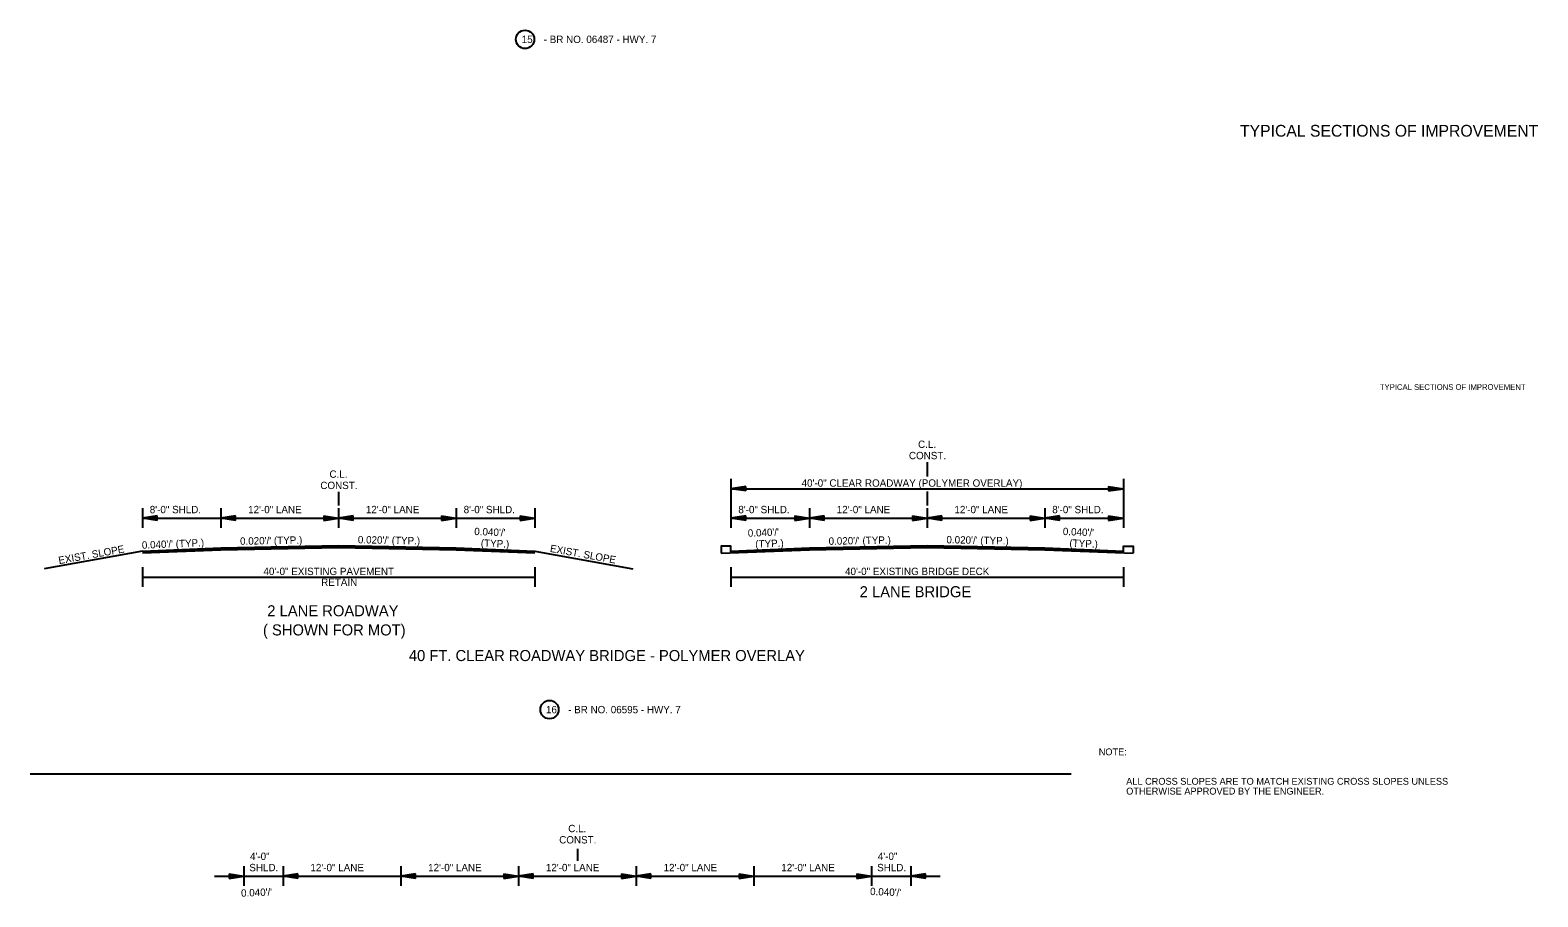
# Model space of a CAD drawing. Extents: x 550980 to 1930787, y -1972975 to 596640.
# Drawn here: x 551009 to 552546, y -1952456 to -1951574 of the extents above; entities that cross this region are included whole.
import ezdxf

# ---------------------------------------------------------------- set-up
doc = ezdxf.new("R2010")
doc.units = 0
for name, color, linetype in [('R_Border', 7, 'Continuous'), ('R_Border Notes', 7, 'Continuous'), ('R_Draft', 7, 'Continuous'), ('S_AREA_CALC', 7, 'Continuous')]:
    doc.layers.add(name, color=color, linetype=linetype)

# ---------------------------------------------------------------- blocks, each defined once
blk = doc.blocks.new('BPPOLY')
at = {"layer": 'R_Border'}
blk.add_circle((0, 0), 9.34, dxfattribs=at)
blk = doc.blocks.new('ARROW')
at = {"layer": 'R_Draft'}
for p, q in [((-2, 0.3), (0, 0)), ((-2, 0.3), (-2, -0.3)), ((-2, 0.25), (-0.334, 0)), ((-2, 0.199), (-0.678, 0)), ((-2, 0.149), (-1.011, 0)), ((-2, 0.097), (-1.35, 0)), ((-2, 0.047), (-1.684, 0)), ((-2, -0.3), (0, 0)), ((-2, -0.098), (-1.35, 0)), ((-2, -0.199), (-0.678, 0)), ((-2, -0.25), (-0.334, 0)), ((-2, -0.149), (-1.011, 0)), ((-2, -0.047), (-1.684, 0))]:
    blk.add_line(p, q, dxfattribs=at)

msp = doc.modelspace()

# ---------------------------------------------------------------- linework, layer by layer
at = {"layer": 'R_Border'}
for p, q in [((551923.4, -1952013.7), (551923.4, -1952028.2)), ((551723.4, -1952030.7), (551723.4, -1952080.7)), ((551723.4, -1952040.7), (552123.4, -1952040.7)), ((552123.4, -1952030.7), (552123.4, -1952080.7)), ((551323.4, -1952043.9), (551323.4, -1952057.7)), ((551923.4, -1952043.7), (551923.4, -1952057.7)), ((551123.4, -1952060.7), (551123.4, -1952080.7)), ((551123.4, -1952070.7), (551523.4, -1952070.7)), ((551203.4, -1952060.7), (551203.4, -1952080.7)), ((551323.4, -1952060.7), (551323.4, -1952080.7)), ((551443.4, -1952060.7), (551443.4, -1952080.7)), ((551523.4, -1952060.7), (551523.4, -1952080.7)), ((551723.4, -1952070.7), (552123.4, -1952070.7)), ((551803.4, -1952060.7), (551803.4, -1952080.7)), ((551923.4, -1952060.7), (551923.4, -1952080.7)), ((552043.4, -1952060.7), (552043.4, -1952080.7)), ((551123.4, -1952104.3), (551023.4, -1952122.3)), ((551523.4, -1952104.3), (551623.4, -1952122.3)), ((551123.4, -1952120.7), (551123.4, -1952140.7)), ((551123.4, -1952130.7), (551523.4, -1952130.7)), ((551523.4, -1952120.7), (551523.4, -1952140.7)), ((551723.4, -1952120.7), (551723.4, -1952140.7)), ((551723.4, -1952130.7), (552123.4, -1952130.7)), ((552123.4, -1952120.7), (552123.4, -1952140.7)), ((551009, -1952331.3), (552070.2, -1952331.3)), ((551566.8, -1952407.6), (551566.8, -1952419.7)), ((551226.8, -1952425.4), (551226.8, -1952445.4)), ((551266.8, -1952425.4), (551266.8, -1952445.4)), ((551386.8, -1952425.4), (551386.8, -1952445.4)), ((551506.8, -1952425.4), (551506.8, -1952445.4)), ((551626.8, -1952425.4), (551626.8, -1952445.4)), ((551746.8, -1952425.4), (551746.8, -1952445.4)), ((551866.8, -1952425.4), (551866.8, -1952445.4)), ((551906.8, -1952425.4), (551906.8, -1952445.4)), ((551196.8, -1952435.4), (551936.8, -1952435.4))]:
    msp.add_line(p, q, dxfattribs=at)
for points in [[(551123.4, -1952104.3), (551203.4, -1952101.1), (551323.4, -1952098.7), (551443.4, -1952101.1), (551523.4, -1952104.3)], [(551123.4, -1952104.6), (551203.4, -1952101.4), (551323.4, -1952099), (551443.4, -1952101.4), (551523.4, -1952104.6)], [(551123.4, -1952104.9), (551203.4, -1952101.7), (551323.4, -1952099.3), (551443.4, -1952101.7), (551523.4, -1952104.9)], [(551123.4, -1952105.2), (551203.4, -1952102), (551323.4, -1952099.6), (551443.4, -1952102), (551523.4, -1952105.2)], [(551123.4, -1952105.5), (551203.4, -1952102.3), (551323.4, -1952099.9), (551443.4, -1952102.3), (551523.4, -1952105.5)], [(551123.4, -1952105.8), (551203.4, -1952102.6), (551323.4, -1952100.2), (551443.4, -1952102.6), (551523.4, -1952105.8)], [(551123.4, -1952106.1), (551203.4, -1952102.9), (551323.4, -1952100.5), (551443.4, -1952102.9), (551523.4, -1952106.1)], [(551723.4, -1952105.8), (551723.4, -1952099.3), (551713.4, -1952099.3), (551713.4, -1952106.5)], [(551713.4, -1952106.5), (551803.4, -1952102.9), (551923.4, -1952100.5), (552043.4, -1952102.9), (552133.4, -1952106.5)], [(551723.4, -1952104.3), (551803.4, -1952101.1), (551923.4, -1952098.7), (552043.4, -1952101.1), (552123.4, -1952104.3)], [(551723.4, -1952104.6), (551803.4, -1952101.4), (551923.4, -1952099), (552043.4, -1952101.4), (552123.4, -1952104.6)], [(551723.4, -1952104.9), (551803.4, -1952101.7), (551923.4, -1952099.3), (552043.4, -1952101.7), (552123.4, -1952104.9)], [(551723.4, -1952105.2), (551803.4, -1952102), (551923.4, -1952099.6), (552043.4, -1952102), (552123.4, -1952105.2)], [(551723.4, -1952105.5), (551803.4, -1952102.3), (551923.4, -1952099.9), (552043.4, -1952102.3), (552123.4, -1952105.5)], [(551723.4, -1952105.8), (551803.4, -1952102.6), (551923.4, -1952100.2), (552043.4, -1952102.6), (552123.4, -1952105.8)], [(552123.4, -1952106.5), (552123.4, -1952099.3), (552133.4, -1952099.3), (552133.4, -1952106.5)]]:
    msp.add_lwpolyline(points, dxfattribs=at)

# ---------------------------------------------------------------- block references
for p in [(551513.5, -1951583), (551538.4, -1952265.7)]:
    msp.add_blockref('BPPOLY', p, dxfattribs=at)
at = {"layer": 'R_Border', "xscale": 7.5, "yscale": 7.5, "rotation": 180}
for p in [(551723.4, -1952040.7), (551123.4, -1952070.7), (551203.4, -1952070.7), (551323.4, -1952070.7), (551723.4, -1952070.7), (551803.4, -1952070.7), (551923.4, -1952070.7), (552043.4, -1952070.7), (551266.8, -1952435.4), (551386.8, -1952435.4), (551506.8, -1952435.4), (551626.8, -1952435.4), (551906.8, -1952435.4)]:
    msp.add_blockref('ARROW', p, dxfattribs=at)
at = {"layer": 'R_Border', "xscale": 7.5, "yscale": 7.5}
for p in [(552123.4, -1952040.7), (551323.4, -1952070.7), (551443.4, -1952070.7), (551523.4, -1952070.7), (551803.4, -1952070.7), (551923.4, -1952070.7), (552043.4, -1952070.7), (552123.4, -1952070.7), (551226.8, -1952435.4), (551506.8, -1952435.4), (551626.8, -1952435.4), (551746.8, -1952435.4), (551866.8, -1952435.4)]:
    msp.add_blockref('ARROW', p, dxfattribs=at)

# ---------------------------------------------------------------- texts
at = {"layer": 'R_Border'}
for s, height, p in [('15', 7.5, (551510.1, -1951586.7)), ('- BR NO. 06487 - HWY. 7', 7.5, (551532.5, -1951586.7)), ('C.L.', 7.5, (551914.1, -1951999.2)), ('CONST.', 7.5, (551904.8, -1952010.7)), ('C.L.', 7.5, (551314.1, -1952029.6)), ('CONST.', 7.5, (551304.8, -1952041.1)), ('40\'-0" CLEAR ROADWAY (POLYMER OVERLAY)', 7.5, (551795.4, -1952038.7)), ('8\'-0" SHLD.', 7.5, (551130.9, -1952065.7)), ('12\'-0" LANE', 7.5, (551231.2, -1952065.7)), ('12\'-0" LANE', 7.5, (551351.2, -1952065.7)), ('8\'-0" SHLD.', 7.5, (551450.9, -1952065.7)), ('8\'-0" SHLD.', 7.5, (551730.9, -1952065.7)), ('12\'-0" LANE', 7.5, (551831.2, -1952065.7)), ('12\'-0" LANE', 7.5, (551951.2, -1952065.7)), ('8\'-0" SHLD.', 7.5, (552050.9, -1952065.7)), ('40\'-0" EXISTING PAVEMENT', 7.5, (551246.8, -1952128.7)), ('RETAIN', 7.5, (551305.6, -1952139.7)), ('40\'-0" EXISTING BRIDGE DECK', 7.5, (551839.7, -1952128.7)), ('2 LANE BRIDGE ', 11.25, (551854.6, -1952151.3)), ('2 LANE ROADWAY', 11.25, (551250.7, -1952170.7)), ('( SHOWN FOR MOT)', 11.25, (551246.3, -1952190.2)), ('40 FT. CLEAR ROADWAY BRIDGE - POLYMER OVERLAY', 11.25, (551395, -1952216.3)), ('16', 7.5, (551534.8, -1952269.5)), ('- BR NO. 06595 - HWY. 7', 7.5, (551557.4, -1952269.5)), ('CONST.', 7.5, (551548.3, -1952402.1)), ('C.L.', 7.5, (551557.5, -1952390.6)), ('4\'-0"', 7.5, (551233.1, -1952418.9)), ('4\'-0"', 7.5, (551873.1, -1952418.9)), ('SHLD.', 7.5, (551232.4, -1952430.4)), ('12\'-0" LANE', 7.5, (551294.7, -1952430.4)), ('12\'-0" LANE', 7.5, (551414.7, -1952430.4)), ('12\'-0" LANE', 7.5, (551534.7, -1952430.4)), ('12\'-0" LANE', 7.5, (551654.7, -1952430.4)), ('12\'-0" LANE', 7.5, (551774.7, -1952430.4)), ('SHLD.', 7.5, (551872.4, -1952430.4))]:
    msp.add_text(s, height=height, dxfattribs=at).set_placement(p)
for s, height, rotation, p in [('TYPICAL SECTIONS OF IMPROVEMENT', 12, 360, (552242.3, -1951682.1)), ("0.020'/' (TYP.)", 7.5, 1.1458, (551223, -1952097.9)), ("0.020'/' (TYP.)", 7.5, 358.8542, (551343, -1952096.3)), ("0.040'/'", 7.5, 357.7084, (551461.6, -1952087.9)), ("0.040'/'", 7.5, 2.2916, (551740.7, -1952089.7)), ("0.020'/' (TYP.)", 7.5, 1.1458, (551823, -1952097.9)), ("0.020'/' (TYP.)", 7.5, 358.8542, (551943, -1952096.3)), ("0.040'/'", 7.5, 357.7084, (552061.6, -1952087.9)), ('EXIST. SLOPE', 7.5, 10.204, (551038.5, -1952117.6)), ("0.040'/' (TYP.)", 7.5, 2.2916, (551123, -1952101.9)), ('(TYP.)', 7.5, 357.7084, (551468.3, -1952099.7)), ('EXIST. SLOPE', 7.5, 349.796, (551538.5, -1952105)), ('(TYP.)', 7.5, 2.2916, (551748.3, -1952100.9)), ('(TYP.)', 7.5, 357.7084, (552068.3, -1952099.7)), ("0.040'/'", 7.5, 2.2916, (551224.1, -1952456.4)), ("0.040'/'", 7.5, 357.7084, (551865.1, -1952454.6))]:
    msp.add_text(s, height=height, rotation=rotation, dxfattribs=at).set_placement(p)
at = {"layer": 'R_Border Notes'}
for s, p in [('NOTE: ', (552098.3, -1952312.3)), ('ALL CROSS SLOPES ARE TO MATCH EXISTING CROSS SLOPES UNLESS ', (552126.3, -1952342.3)), ('OTHERWISE APPROVED BY THE ENGINEER.', (552126.3, -1952352.3))]:
    msp.add_text(s, height=7, dxfattribs=at).set_placement(p)
at = {"layer": 'S_AREA_CALC'}
msp.add_text('TYPICAL SECTIONS OF IMPROVEMENT', height=5.862, rotation=360, dxfattribs=at).set_placement((552384.9, -1951940.1))

doc.saveas('drawing.dxf')
